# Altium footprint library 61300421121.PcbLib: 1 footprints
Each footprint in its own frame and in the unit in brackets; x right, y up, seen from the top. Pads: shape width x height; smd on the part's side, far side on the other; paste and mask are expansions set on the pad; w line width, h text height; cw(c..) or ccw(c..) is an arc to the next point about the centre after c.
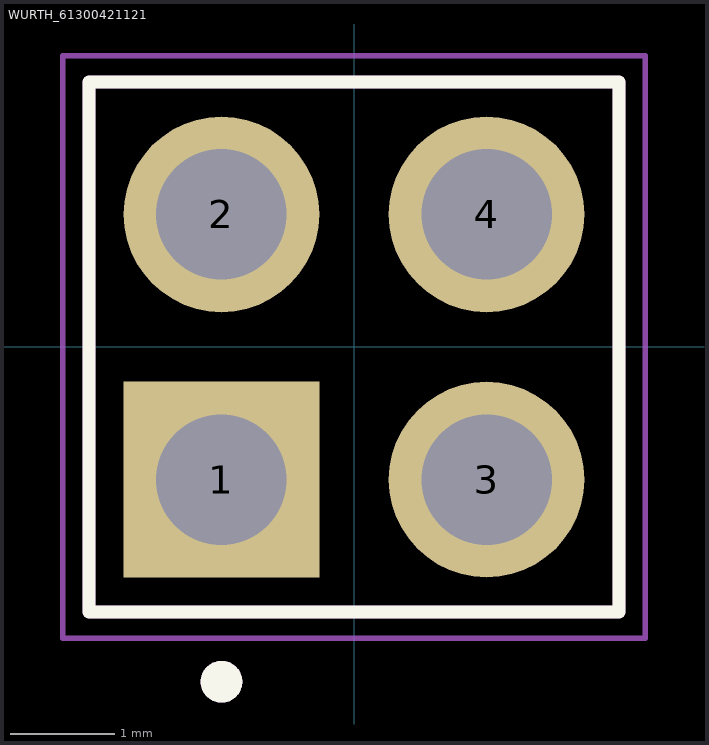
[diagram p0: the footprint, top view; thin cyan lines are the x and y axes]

## WURTH_61300421121 [mm]
height 8.89
pads (4):
  rect 1.875x1.875 / inner round 1.875 / far side rect 1.875x1.875 hole 1.25: 1(-1.27,-1.27)
  round 1.875 hole 1.25: 2(-1.27,1.27) 3(1.27,-1.27) 4(1.27,1.27)
Top Overlay:
  circle w0.2: c-1.27,-3.207 r0.1
  lines w0.127: -2.54,-2.54 -2.54,2.54 2.54,2.54 2.54,-2.54 -2.54,-2.54
Assembly Top:
  circle w0.2: c-1.27,-3.207 r0.1
  lines w0.127: -2.54,-2.54 -2.54,2.54 2.54,2.54 2.54,-2.54 -2.54,-2.54
Courtyard Top:
  lines w0.05: -2.79,-2.79 -2.79,2.79 2.79,2.79 2.79,-2.79 -2.79,-2.79
3D body "step_temp.STEP": height 7.27, standoff -4.27, extent -2.54,-1.27 2.54,3.81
